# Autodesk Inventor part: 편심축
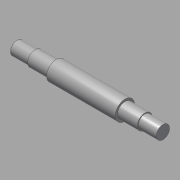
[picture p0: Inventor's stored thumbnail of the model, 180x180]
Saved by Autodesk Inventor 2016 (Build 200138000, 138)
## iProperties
Created: 2015-10
Part Number: 편심축
Document SubType Name: Modeling
Designer: mdu
Density: 7.86 g/cm^3
Material: 강철, 연강
Mass: 1163.82 g
Surface Area: 210.981 cm^2
Volume: 148.069 cm^3
Appearance: 강철
Author: mdu
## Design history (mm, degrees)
sketch "스케치1"
  geometry: L1 (-20.5, -41.331)-(-20.5, 32.669) reference; L2 (7.5, -30.031)-(7.5, 21.369) reference; L3 (135.5, -30.331)-(135.5, 21.669) reference; L4 (121.5, 21.369)-(121.5, -30.031) reference; L5 (184.5, -4.331)-(-7.5, -4.331); L6 (184.5, -4.331)-(184.5, 6.669); L7 (154.5, 8.169)-(121.5, 8.169); L8 (121.5, 8.169)-(121.5, 11.669); L9 (121.5, 11.669)-(7.5, 11.669); L10 (7.5, 11.669)-(7.5, 8.169); L11 (7.5, 8.169)-(-7.5, 8.169); L12 (-7.5, 8.169)-(-7.5, -4.331); L13 (154.5, 8.169)-(154.5, 6.669); L14 (154.5, 6.669)-(184.5, 6.669); C1 r 32.5 at (64.5, -4.331) reference; 1 further point
  constraints: 21 end point, 8 perpendicular, 5 point on line, 1 collinear
  dimensions: "d1" = 25 diameter of L11 L5; "d2" = 32 diameter of L9 L5; "d4" = 15 distance of L10.end L11.end; "d15" = 33 distance of L7.start L7.end; "d26" = 30 distance of L13.end L6.end; "d36" = 22 diameter of L14 L5
revolve "회전1" sketch "스케치1" stored, may be unused: angle "d6" = 90 deg
node "작업 평면1"
sketch "스케치2"
  geometry: C1 r 16 at (0, 0) reference; C2 r 20.75 at (0, 4)
  constraints: 1 centre point, 1 vertical alignment
  dimensions: "d34" = 4 distance of C2.centre C1.centre; "d35" = 41.5 diameter of C2
extrude "돌출1" join sketch "스케치2" stored distance "d9" = 40; taper "d10" = 0 deg
chamfer "모따기1" distance "d11" = 1; stored, may be unused: second distance "d12" = 2, angle "d13" = 45 deg
node "작업 평면2"
sketch "스케치3"
  geometry: L1 (-15, -10)-(-15, 10) reference; L2 (-15, 3)-(0, 3); L3 (0, -3)-(-15, -3); A1 r 3 centre (0, 0) between (0, -3) and (0, 3); 2 further points
  constraints: 4 end point, 2 perpendicular, 2 point on circle, 2 point on line, 2 tangent, 1 centre point, 1 horizontal alignment, 1 midpoint
  dimensions: "d16" = 18 dimension on A1 L1; "d17" = 6 distance between parallel lines of L3 L2
extrude "돌출2" cut sketch "스케치3" distance "d18" = 3.5; taper "d19" = 0 deg
node "솔리드1"
node "참조1"
node "참조2"
node "참조3"
node "참조4"
node "참조5"
other parameters: "d30" = 35
